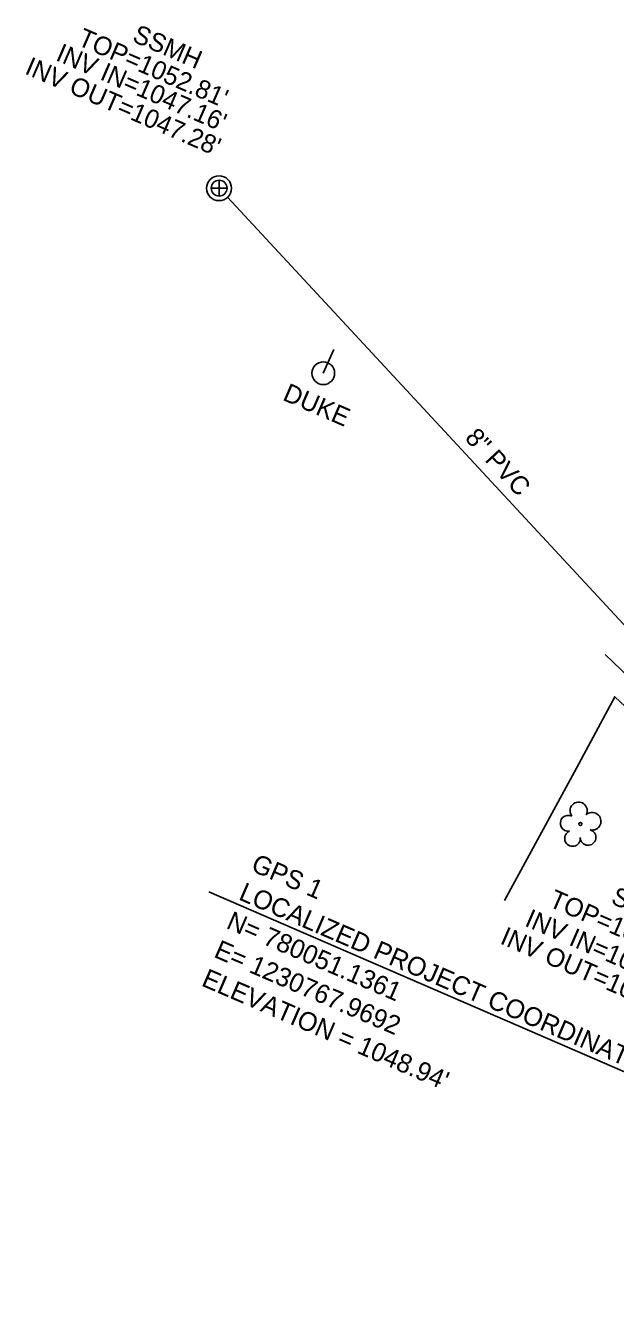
# Model space of a CAD drawing. Extents: x 1230592 to 1231575, y 779497 to 780221.
# Drawn here: x 1230592.4 to 1230719.7, y 779941.5 to 780220.6 of the extents above; entities that cross this region are included whole.
import ezdxf

# ---------------------------------------------------------------- set-up
doc = ezdxf.new("R2010")
doc.units = 0
for name, color, linetype in [('CTL Supplemental Horizontal and Vertical Text', 7, 'Continuous'), ('Default', 7, 'Continuous'), ('Exist Other Culture Fence Line', 7, 'Continuous'), ('Exist Utilities Power Pole CELL', 7, 'Continuous'), ('Exist Utilities Power Pole Text', 7, 'Continuous'), ('Exist Utilities Sanitary Sewer Manhole CELL', 7, 'Continuous'), ('Exist Utilities Sanitary Sewer Manhole Text', 7, 'Continuous'), ('Exist Utilities Sanitary Sewer UG Line', 7, 'Continuous'), ('Exist Utilities Sanitary Sewer UG Line Invert Elevation', 7, 'Continuous'), ('Exist Utilities Sanitary Sewer UG Line Text', 7, 'Continuous'), ('Exist Utilities Telephone UG FO SUE', 7, 'Continuous'), ('Exist Vegetation Tree CELL', 7, 'Continuous')]:
    doc.layers.add(name, color=color, linetype=linetype)

msp = doc.modelspace()

# ---------------------------------------------------------------- linework, layer by layer
at = {"layer": 'Default'}
msp.add_line((1230743.44, 779985.31), (1230631.91, 780033.62), dxfattribs=at)
at = {"layer": 'Exist Other Culture Fence Line'}
msp.add_lwpolyline([(1230880.25, 779941.6), (1230853.18, 779957.14), (1230835.11, 779971.4), (1230810.95, 779991.8), (1230792.98, 780007.87), (1230757.31, 780040.54), (1230719.63, 780075.75), (1230711.33, 780060.3), (1230695.77, 780031.77)], dxfattribs=at)
at = {"layer": 'Exist Utilities Power Pole CELL'}
for q in [(1230658.91, 780150.77), (1230656.65, 780145.62)]:
    msp.add_line((1230656.65, 780145.62), q, dxfattribs=at)
msp.add_circle((1230656.65, 780145.62), 2.45, dxfattribs=at)
at = {"layer": 'Exist Utilities Sanitary Sewer Manhole CELL'}
msp.add_lwpolyline([(1230634.13, 780187.29), (1230634.13, 780183.87), (1230634.13, 780185.58), (1230635.85, 780185.58), (1230632.42, 780185.58)], dxfattribs=at)
for radius in [2.69, 1.71]:
    msp.add_circle((1230634.13, 780185.58), radius, dxfattribs=at)
at = {"layer": 'Exist Utilities Sanitary Sewer UG Line'}
msp.add_line((1230761.76, 780048.01), (1230635.96, 780183.61), dxfattribs=at)
at = {"layer": 'Exist Utilities Telephone UG FO SUE'}
msp.add_lwpolyline([(1230717.56, 780084.84), (1230755.17, 780048.89), (1230793.32, 780015.51), (1230834.26, 779983.7), (1230859.68, 779966.46), (1230875.86, 779956.24), (1230911.92, 779932.25), (1230957.32, 779909.15), (1230963.62, 779906.34), (1230967.97, 779905.69), (1230971.46, 779906.77), (1230971.4, 779908.18)], dxfattribs=at)
at = {"layer": 'Exist Vegetation Tree CELL'}
msp.add_line((1230712.19, 780048.27), (1230712.19, 780048.27), dxfattribs=at)
msp.add_circle((1230712.19, 780048.27), 0.326, dxfattribs=at)
for centre, radius, start, end in [((1230711.81, 780051.15), 1.86, 330.1651, 219.7134), ((1230709.58, 780048.43), 1.73, 62.6636, 279.3457), ((1230714.74, 780048.86), 1.9, 257.1011, 134.1999), ((1230710.49, 780045.15), 1.69, 111.5671, 6.231), ((1230713.86, 780045.37), 1.7, 181.2822, 74.56)]:
    msp.add_arc(centre, radius, start, end, dxfattribs=at)

# ---------------------------------------------------------------- texts
at = {"layer": 'CTL Supplemental Horizontal and Vertical Text'}
for s, p in [('GPS 1', (1230640.8, 780038.24)), ('LOCALIZED PROJECT COORDINATES', (1230638.13, 780032.04)), ('N= 780051.1361', (1230635.45, 780025.84)), ('E= 1230767.9692', (1230632.77, 780019.63)), ("ELEVATION = 1048.94'", (1230630.09, 780013.43))]:
    msp.add_text(s, height=4.055, rotation=336.6486, dxfattribs=at).set_placement(p)
at = {"layer": 'Exist Utilities Power Pole Text'}
msp.add_text('DUKE', height=4, rotation=336.5812, dxfattribs=at).set_placement((1230647.64, 780139.91))
at = {"layer": 'Exist Utilities Sanitary Sewer Manhole Text'}
for s, p in [("TOP=1052.81'", (1230603.31, 780216.6)), ('SSMH', (1230615.14, 780217.37)), ("TOP=1049.24'", (1230705.14, 780030.57)), ('SSMH', (1230718.56, 780031.2))]:
    msp.add_text(s, height=4, rotation=336.5812, dxfattribs=at).set_placement(p)
at = {"layer": 'Exist Utilities Sanitary Sewer UG Line Invert Elevation'}
for s, p in [("INV IN=1047.16'", (1230598.62, 780213.3)), ("INV OUT=1047.28'", (1230591.92, 780210.39)), ("INV IN=1042.55'", (1230699.94, 780026.37)), ("INV OUT=1042.46'", (1230694.62, 780022.53))]:
    msp.add_text(s, height=4, rotation=336.5812, dxfattribs=at).set_placement(p)
at = {"layer": 'Exist Utilities Sanitary Sewer UG Line Text'}
msp.add_text('8" PVC', height=4, rotation=312.8528, dxfattribs=at).set_placement((1230687.05, 780131.48))

doc.saveas('drawing.dxf')
